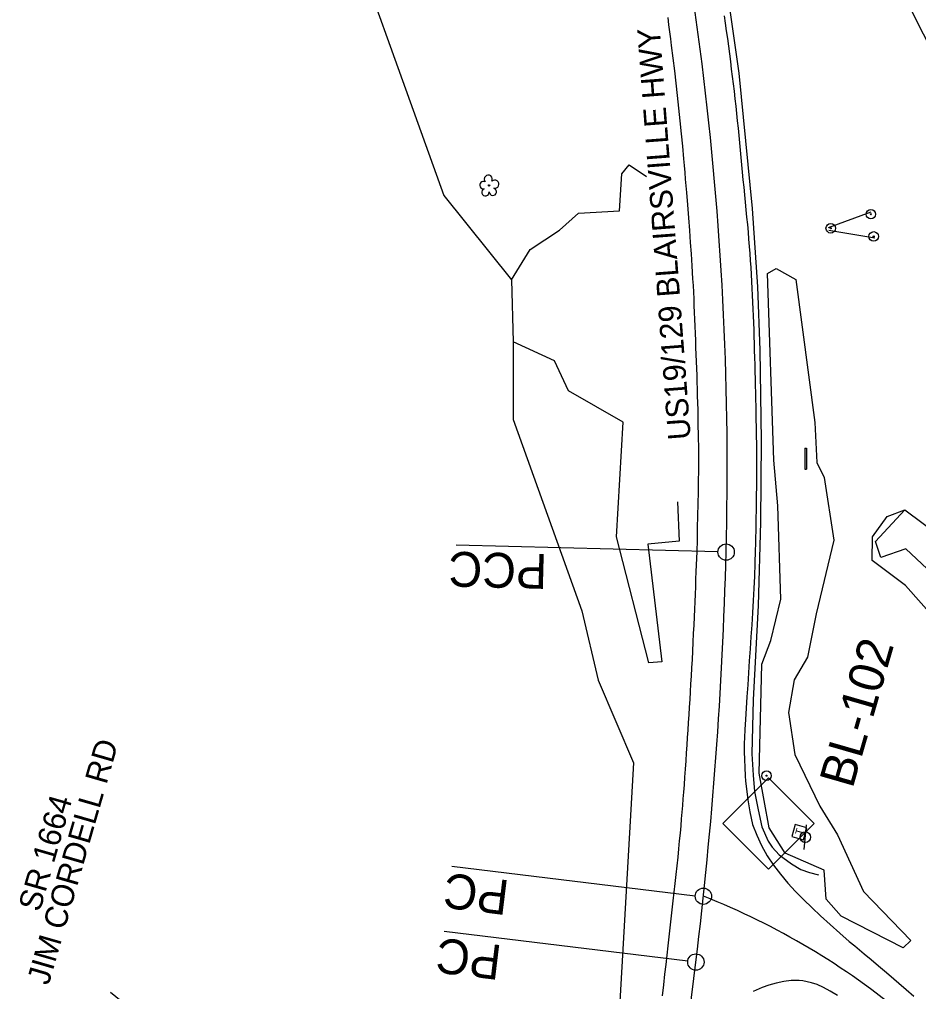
# Model space of a CAD drawing. Extents: x 479429 to 482809, y 488118 to 492379.
# Drawn here: x 481087.8 to 481500.1, y 491143.2 to 491589 of the extents above; entities that cross this region are included whole.
import ezdxf

# ---------------------------------------------------------------- set-up
doc = ezdxf.new("R2010")
doc.units = 0
for name, color, linetype in [('CTL Secondary Horizontal and Vertical CELL', 7, 'Continuous'), ('CTL Secondary Horizontal and Vertical Text', 7, 'Continuous'), ('Exist Guardrail', 7, 'Continuous'), ('Exist Horizontal Alignment', 7, 'Continuous'), ('Exist Other Culture Sign', 7, 'Continuous'), ('Exist Other Culture Sign Post CELL', 7, 'Continuous'), ('Exist Roads EOP', 7, 'Continuous'), ('Exist Roads EOP Text', 7, 'Continuous'), ('Exist Structure Major Bridge WW', 7, 'Continuous'), ('Exist Structure Minor Head and End Wall', 7, 'Continuous'), ('Exist Utilities Telephone Pedestal CELL', 7, 'Continuous'), ('Exist Utilities Telephone Pole CELL', 7, 'Continuous'), ('Exist Vegetation Hedge Row', 7, 'Continuous'), ('Exist Vegetation Tree CELL', 7, 'Continuous'), ('Exist Vegetation Woods Line', 7, 'Continuous')]:
    doc.layers.add(name, color=color, linetype=linetype)

msp = doc.modelspace()

# ---------------------------------------------------------------- linework, layer by layer
at = {"layer": 'CTL Secondary Horizontal and Vertical CELL'}
msp.add_line((481431.11, 491220.21), (481431.11, 491220.21), dxfattribs=at)
msp.add_lwpolyline([(481410.25, 491220.28), (481431.22, 491241.24), (481452.22, 491220.24), (481431.25, 491199.28)], close=True, dxfattribs=at)
at = {"layer": 'Exist Guardrail'}
for points in [[(481401.12, 491670.96), (481408.83, 491626.51), (481417.64, 491564.33), (481423.77, 491502.24), (481426.23, 491466.29), (481427.33, 491437.29), (481427.85, 491395.94), (481427.63, 491358.35), (481426.51, 491320.15)], [(481426.51, 491320.15), (481424.29, 491276.88), (481423.65, 491252.13), (481424.2, 491242.46), (481424.86, 491234.96), (481426.53, 491226.56), (481428.17, 491218.69), (481431.06, 491212.09), (481432.94, 491209.45), (481436.2, 491205.86), (481441.88, 491201.69), (481446.03, 491199.17), (481450.06, 491197.79), (481454.12, 491196.76)]]:
    msp.add_lwpolyline(points, dxfattribs=at)
at = {"layer": 'Exist Horizontal Alignment'}
for p, q in [((481408.09, 491344.79), (481288.1, 491347.9)), ((481397.65, 491186.9), (481286.01, 491200.53)), ((481394.23, 491157.16), (481282.59, 491170.79)), ((481201.31, 489545.89), (481397.95, 491156.7))]:
    msp.add_line(p, q, dxfattribs=at)
for centre in [(481411.84, 491344.69), (481401.4, 491186.9), (481397.95, 491156.7)]:
    msp.add_circle(centre, 3.75, dxfattribs=at)
for centre, radius, start, end in [((479919.39, 491383.43), 1492.95, 358.51314, 15.21582), ((479438.51, 491395.91), 1973.99, 353.03983, 358.51314), ((481278.32, 490874.73), 335.56, 50.0189, 68.4821)]:
    msp.add_arc(centre, radius, start, end, dxfattribs=at)
at = {"layer": 'Exist Other Culture Sign'}
for p, q in [((481458.84, 491493.59), (481478.28, 491500.76)), ((481480, 491488.72), (481458.85, 491492.17))]:
    msp.add_line(p, q, dxfattribs=at)
at = {"layer": 'Exist Other Culture Sign Post CELL'}
for centre, radius in [((481478.19, 491499.65), 2.18), ((481478.19, 491499.65), 0.24), ((481459.8, 491493.18), 2.18), ((481459.8, 491493.18), 0.24), ((481479.49, 491489.47), 2.18), ((481479.49, 491489.47), 0.24), ((481430.37, 491242.17), 2.18), ((481430.37, 491242.17), 0.24)]:
    msp.add_circle(centre, radius, dxfattribs=at)
at = {"layer": 'Exist Roads EOP'}
for points in [[(481382.63, 491141.21), (481383.2, 491146.33), (481383.75, 491151.12), (481384.27, 491155.58), (481384.78, 491159.85), (481385.27, 491164.09), (481385.74, 491168.28), (481386.2, 491172.43), (481386.66, 491176.55), (481387.12, 491180.64), (481387.58, 491184.71), (481388.05, 491188.76), (481388.51, 491192.79), (481388.95, 491196.79), (481389.37, 491200.78), (481389.78, 491204.75), (481390.16, 491208.62), (481390.52, 491212.31), (481390.85, 491215.81), (481391.15, 491219.12), (481391.43, 491222.32), (481391.7, 491225.45), (481391.96, 491228.52), (481392.2, 491231.53), (481392.44, 491234.62), (481392.69, 491237.92), (481392.94, 491241.43), (481393.2, 491245.15), (481393.46, 491248.92), (481393.7, 491252.6), (481393.94, 491256.18), (481394.16, 491259.65), (481394.37, 491263.09), (481394.59, 491266.54), (481394.82, 491270.02), (481395.05, 491273.52), (481395.28, 491277.05), (481395.5, 491280.61), (481395.72, 491284.22), (481395.93, 491287.86), (481396.14, 491291.57), (481396.35, 491295.4), (481396.55, 491299.34), (481396.75, 491303.39), (481396.95, 491307.41), (481397.13, 491311.26), (481397.29, 491314.95), (481397.44, 491318.47), (481397.58, 491321.92), (481397.72, 491325.37), (481397.87, 491328.82), (481398.01, 491332.29), (481398.15, 491335.67), (481398.27, 491338.89), (481398.49, 491344.82), (481398.65, 491350.37), (481398.76, 491355.82), (481398.86, 491361.27), (481398.99, 491366.84), (481399.11, 491372.27), (481399.2, 491377.29), (481399.27, 491382.13), (481399.29, 491387.01), (481399.27, 491392.13), (481399.2, 491397.73), (481399.09, 491403.71), (481399.02, 491406.82), (481398.95, 491410.01), (481398.86, 491413.22), (481398.77, 491416.39), (481398.68, 491419.53), (481398.59, 491422.64), (481398.48, 491425.74), (481398.38, 491428.88), (481398.26, 491432.06), (481398.14, 491435.28), (481398.02, 491438.52), (481397.9, 491441.75), (481397.77, 491444.99), (481397.65, 491448.23), (481397.52, 491451.45), (481397.39, 491454.64), (481397.25, 491457.78), (481397.11, 491460.89), (481396.96, 491463.97), (481396.81, 491467.01), (481396.64, 491470.03), (481396.28, 491475.92), (481395.92, 491481.42), (481395.56, 491486.6), (481395.18, 491492.12), (481394.76, 491498.02), (481394.3, 491503.88), (481393.79, 491509.67), (481393.53, 491512.65), (481393.26, 491515.71), (481392.98, 491518.83), (481392.71, 491521.96), (481392.43, 491525), (481391.91, 491530.83), (481391.37, 491536.57), (481390.79, 491542.45), (481390.18, 491548.34), (481389.55, 491554.1), (481388.9, 491559.78), (481388.24, 491565.46), (481387.56, 491571.2), (481386.85, 491577.07), (481386.47, 491580.09), (481386.07, 491583.23), (481385.64, 491586.48), (481385.19, 491589.85)], [(481410.98, 491590.58), (481411.45, 491587.19), (481411.92, 491583.74), (481412.39, 491580.25), (481412.87, 491576.71), (481413.33, 491573.17), (481413.78, 491569.67), (481414.22, 491566.21), (481414.65, 491562.79), (481415.06, 491559.39), (481415.47, 491556), (481415.86, 491552.61), (481416.24, 491549.23), (481416.61, 491545.85), (481416.96, 491542.48), (481417.29, 491539.12), (481417.6, 491535.77), (481417.9, 491532.42), (481418.22, 491529.06), (481418.54, 491525.67), (481418.87, 491522.28), (481419.21, 491518.87), (481419.55, 491515.45), (481419.89, 491512.03), (481420.23, 491508.59), (481420.57, 491505.15), (481420.91, 491501.72), (481421.24, 491498.29), (481421.56, 491494.87), (481421.87, 491491.48), (481422.15, 491488.13), (481422.42, 491484.84), (481422.67, 491481.59), (481422.9, 491478.37), (481423.11, 491475.17), (481423.31, 491471.97), (481423.5, 491468.79), (481423.68, 491465.61), (481423.84, 491462.45), (481423.99, 491459.28), (481424.13, 491456.13), (481424.25, 491452.98), (481424.37, 491449.83), (481424.47, 491446.68), (481424.57, 491443.53), (481424.65, 491440.37), (481424.74, 491437.16), (481424.84, 491433.92), (481424.93, 491430.64), (481425.03, 491427.36), (481425.11, 491424.13), (481425.19, 491420.94), (481425.26, 491417.81), (481425.33, 491414.69), (481425.39, 491411.57), (481425.46, 491408.44), (481425.53, 491405.31), (481425.59, 491402.21), (481425.64, 491399.15), (481425.72, 491393.19), (481425.76, 491387.35), (481425.75, 491381.55), (481425.71, 491375.71), (481425.65, 491369.72), (481425.61, 491366.68), (481425.57, 491363.64), (481425.53, 491360.6), (481425.48, 491357.55), (481425.43, 491354.5), (481425.37, 491351.46), (481425.29, 491348.43), (481425.21, 491345.41), (481425.03, 491339.46), (481424.83, 491333.67), (481424.6, 491328.01), (481424.29, 491322.44), (481423.93, 491316.92), (481423.56, 491311.41), (481423.18, 491305.89), (481422.81, 491300.35), (481422.44, 491294.81), (481422.08, 491289.27), (481421.72, 491283.77), (481421.38, 491278.37), (481421.06, 491273.08), (481420.75, 491267.91), (481420.48, 491263.31), (481420.27, 491259.72), (481420.12, 491256.95), (481420.07, 491253.13), (481420.19, 491249.64), (481420.36, 491245.93), (481420.56, 491242.09), (481420.76, 491239.64), (481421.15, 491236.11), (481421.86, 491231.09), (481422.74, 491225.59), (481424, 491219.84), (481425.85, 491214.9), (481428.11, 491210.1), (481430.68, 491205.48), (481433.58, 491201.13), (481436.77, 491196.94), (481440.09, 491192.92), (481443.57, 491189.11), (481447.3, 491185.35), (481451.21, 491181.53), (481455.14, 491177.86), (481459.46, 491173.99), (481463.91, 491170.01), (481468.29, 491166.17), (481470.78, 491164.1), (481475.12, 491160.52), (481478.35, 491157.83), (481481.72, 491155.02), (481484.45, 491152.74), (481486.48, 491151.06), (481490.96, 491147.08), (481494.33, 491144.1), (481497.9, 491141.06)], [(481462.97, 491141.34), (481459.58, 491143.34), (481456.48, 491145), (481453.54, 491146.35), (481450.97, 491147.24), (481447.05, 491148.12), (481445.34, 491148.29), (481441.68, 491148.29), (481438.33, 491147.83), (481434.72, 491147.04), (481431.37, 491146.09), (481428.35, 491144.98), (481424.27, 491143.16)]]:
    msp.add_lwpolyline(points, dxfattribs=at)
at = {"layer": 'Exist Structure Major Bridge WW'}
for p, q in [((481447.99, 491392.34), (481447.95, 491382.77)), ((481448.74, 491392.34), (481448.69, 491382.77))]:
    msp.add_line(p, q, dxfattribs=at)
at = {"layer": 'Exist Structure Minor Head and End Wall'}
for p, q in [((481447.99, 491392.34), (481448.74, 491392.34)), ((481447.95, 491382.77), (481448.69, 491382.77))]:
    msp.add_line(p, q, dxfattribs=at)
at = {"layer": 'Exist Utilities Telephone Pedestal CELL'}
msp.add_line((481445.38, 491216.21), (481445.38, 491216.21), dxfattribs=at)
msp.add_lwpolyline([(481447.35, 491212.82), (481448.88, 491218.2), (481443.49, 491219.73), (481441.97, 491214.34), (481447.35, 491212.82)], dxfattribs=at)
at = {"layer": 'Exist Utilities Telephone Pole CELL'}
for p, q in [((481447.68, 491208.31), (481448.63, 491219.61)), ((481448.16, 491213.97), (481448.16, 491213.97))]:
    msp.add_line(p, q, dxfattribs=at)
msp.add_circle((481448.16, 491213.97), 2.41, dxfattribs=at)
at = {"layer": 'Exist Vegetation Hedge Row'}
for points in [[(481313.47, 491469.61), (481322.04, 491483.41), (481335.43, 491492.31), (481344.18, 491500.08), (481362.98, 491501.15), (481364.06, 491518.17), (481367.38, 491522.21), (481375.3, 491516.91)], [(481436.87, 491323.1), (481435.57, 491365.9), (481433.7, 491386.89), (481430.73, 491472.47), (481434.84, 491474.81), (481443.74, 491469.67), (481452.5, 491404.2), (481453.43, 491385.77), (481456.72, 491378.85), (481461.16, 491350.18), (481453.17, 491316.42)], [(481389.49, 491367.78), (481390.24, 491349.71), (481376, 491348.29), (481382.32, 491294.32), (481376.43, 491293.9), (481361.62, 491351.67), (481364.7, 491404.32), (481339.52, 491418.7), (481333.12, 491432.45), (481314.15, 491441.11)], [(481494.08, 491329.32), (481478.83, 491340.92), (481478.87, 491351.75), (481485.73, 491360.95), (481493.74, 491364.01)], [(481617.28, 491339.62), (481618.64, 491323.95), (481603.09, 491303.76), (481572.11, 491290.56), (481540.69, 491276.86), (481494.08, 491329.32)], [(481464.65, 491177.76), (481457.69, 491185.5), (481456.78, 491198.86), (481438.9, 491206.7), (481431.54, 491218.32), (481426.94, 491243.27), (481428.16, 491293.33), (481432.38, 491304.17), (481436.87, 491323.1)], [(481453.17, 491316.42), (481449.15, 491296.45), (481443.04, 491286.05), (481440.41, 491271.18), (481443.29, 491251.89), (481454.8, 491228.25), (481462.97, 491215), (481474.85, 491188.99), (481496.51, 491166.63), (481493.06, 491163.21), (481464.65, 491177.76)]]:
    msp.add_lwpolyline(points, dxfattribs=at)
at = {"layer": 'Exist Vegetation Tree CELL'}
msp.add_line((481303.18, 491512.84), (481303.18, 491512.84), dxfattribs=at)
msp.add_circle((481303.18, 491512.84), 0.326, dxfattribs=at)
for centre, radius, start, end in [((481302.79, 491515.71), 1.86, 330.1651, 219.7134), ((481300.57, 491513), 1.73, 62.6636, 279.3457), ((481305.73, 491513.43), 1.9, 257.1011, 134.1999), ((481301.47, 491509.72), 1.69, 111.5671, 6.231), ((481304.85, 491509.94), 1.7, 181.2822, 74.56)]:
    msp.add_arc(centre, radius, start, end, dxfattribs=at)
at = {"layer": 'Exist Vegetation Woods Line'}
for points in [[(481715.92, 491548.03), (481655.56, 491556.63), (481652.98, 491487.61), (481645.37, 491491.07), (481641.06, 491503.13), (481603.02, 491495.32), (481599.89, 491436.51), (481578.76, 491430.82), (481464.14, 491658.01), (481431.48, 491691.49), (481406.6, 491708.09), (481372.15, 491848.28)], [(481174.3, 491827.64), (481197.58, 491770.74), (481224.52, 491714.81), (481238.58, 491709.7), (481241.27, 491698.34), (481226.96, 491662.82), (481282.38, 491508.17), (481313.47, 491469.61), (481314.15, 491441.11), (481314.19, 491405.5), (481345.68, 491317.77)], [(481528.63, 491338.12), (481538.18, 491323.51), (481537.16, 491316.59), (481548.77, 491311.4), (481543.06, 491304.95), (481521.15, 491320.9), (481494.16, 491346.18), (481482.71, 491342.26), (481480.27, 491349.57), (481493.74, 491364.01), (481528.63, 491338.12)], [(481345.68, 491317.77), (481353.11, 491285.94), (481369.31, 491248.07), (481358.47, 491058.43), (481341.15, 491052.66), (481321.21, 491054.95), (481298.3, 491063.81), (481271.21, 491099.5), (481228.18, 491111.26), (481224.55, 491104.53), (481200.99, 491109.54), (481185.6, 491126.62), (481153.65, 491129.73), (481134.53, 491138.7), (481129.51, 491142.77)]]:
    msp.add_lwpolyline(points, dxfattribs=at)

# ---------------------------------------------------------------- texts
at = {"layer": 'CTL Secondary Horizontal and Vertical Text'}
msp.add_text('BL-102', height=16, rotation=73.904, dxfattribs=at).set_placement((481469.77, 491235.89))
at = {"layer": 'Exist Horizontal Alignment'}
for s, rotation, p in [('PCC', 178.5131, (481329.97, 491343.78)), ('PC', 173.0398, (481312.95, 491194.05)), ('PC', 173.0398, (481309.53, 491164.3))]:
    msp.add_text(s, height=16, rotation=rotation, dxfattribs=at).set_placement(p)
at = {"layer": 'Exist Roads EOP Text'}
for s, rotation, p in [('US19/129 BLAIRSVILLE HWY', 94.319, (481395.66, 491396.52)), ('JIM CORDELL RD', 73.9281, (481101.17, 491145.71)), ('SR 1664', 73.9281, (481097.14, 491179.34))]:
    msp.add_text(s, height=10.4, rotation=rotation, dxfattribs=at).set_placement(p)
at = {"layer": 'Exist Utilities Telephone Pedestal CELL'}
msp.add_text('T', height=3.42, rotation=74.1954, dxfattribs=at).set_placement((481446.72, 491214.66))

doc.saveas('drawing.dxf')
